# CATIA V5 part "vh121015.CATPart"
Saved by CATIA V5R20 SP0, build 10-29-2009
Part number: VA_12-antigiro3d web
Revision: ANY
Definition: UNKNOWN
Nomenclature: VA_12-antigiro3d web
Source: Unknown
Bounding box of the stored display mesh (mm): x -6 to 5.944, y -3 to 12, z -6 to 6
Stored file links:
  C:\Users\Utente\Desktop\IO LAVORO\3D X SITO CF\CUMSA\3D files VH\vh121015.CATPart
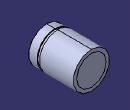
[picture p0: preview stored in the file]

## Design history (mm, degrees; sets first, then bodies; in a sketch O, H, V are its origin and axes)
Body1 "VA-12 Obturador_aire3d web-1-solid1" (main body)
  Solid1: solid without history
Body2 "VA-12_variante_antigiro3d web-1-solid1"
  Solid2: solid without history
Body3 "VA-12_Tuerca_giro_v23d web-1-solid1"
  Solid3: solid without history
Body4 "VA-12 tapa3d web-2-solid1"
  Solid4: solid without history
